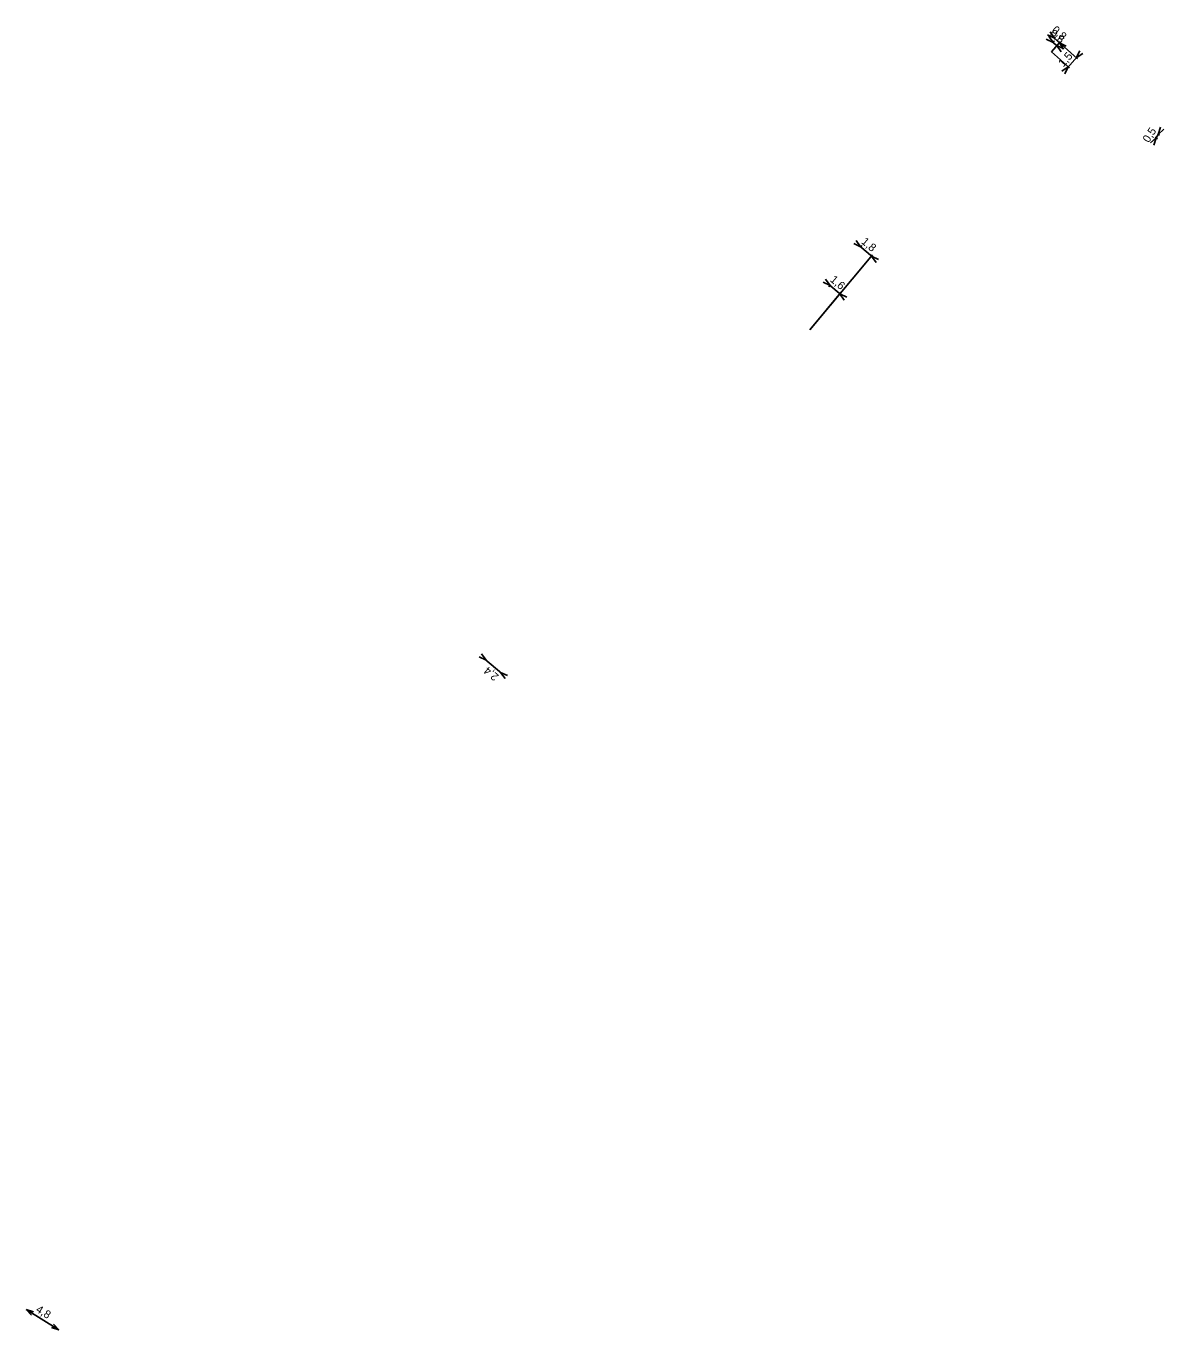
# Model space of a CAD drawing. Extents: x -742845 to -742557, y -1054636 to -1054473.
# Drawn here: x -742845.3 to -742703.1, y -1054636.1 to -1054473.2 of the extents above; entities that cross this region are included whole.
import ezdxf

# ---------------------------------------------------------------- set-up
doc = ezdxf.new("R2010")
doc.units = 0
doc.layers.add('Kota_NN', color=7, linetype='Continuous')
doc.layers.add('Kota_VN', color=7, linetype='Continuous')

msp = doc.modelspace()

# ---------------------------------------------------------------- linework, layer by layer
at = {"layer": 'Kota_NN'}
for p, q in [((-742716.96, -1054475.21), (-742717.82, -1054474.79)), ((-742716.96, -1054475.21), (-742717.5, -1054474.41)), ((-742717.11, -1054475.08), (-742716.36, -1054475.73)), ((-742716.99, -1054475.24), (-742716.83, -1054475.06)), ((-742716.54, -1054475.63), (-742716.38, -1054475.45)), ((-742716.51, -1054475.6), (-742715.64, -1054476.02)), ((-742716.51, -1054475.6), (-742715.97, -1054476.39)), ((-742703.83, -1054486.7), (-742703.54, -1054485.79)), ((-742703.83, -1054486.7), (-742703.12, -1054486.06)), ((-742704.1, -1054487.12), (-742704.81, -1054487.77)), ((-742704.1, -1054487.12), (-742704.4, -1054488.04)), ((-742704.21, -1054487.29), (-742703.72, -1054486.53)), ((-742704.21, -1054487.05), (-742703.93, -1054487.23)), ((-742703.94, -1054486.63), (-742703.66, -1054486.81))]:
    msp.add_line(p, q, dxfattribs=at)
at = {"layer": 'Kota_VN'}
for p, q in [((-742716.8, -1054474.69), (-742717.66, -1054474.26)), ((-742716.8, -1054474.69), (-742717.33, -1054473.89)), ((-742716.95, -1054474.55), (-742716.04, -1054475.37)), ((-742716.81, -1054474.69), (-742716.67, -1054474.54)), ((-742716.81, -1054474.69), (-742713.92, -1054477.25)), ((-742717.19, -1054476.37), (-742716.05, -1054475.09)), ((-742717.19, -1054476.37), (-742714.92, -1054478.38)), ((-742716.19, -1054475.24), (-742715.33, -1054475.67)), ((-742716.19, -1054475.24), (-742715.66, -1054476.04)), ((-742714.07, -1054477.12), (-742713.64, -1054476.26)), ((-742715.2, -1054478.4), (-742713.94, -1054476.97)), ((-742714.07, -1054477.12), (-742713.27, -1054476.59)), ((-742715.07, -1054478.25), (-742715.87, -1054478.78)), ((-742715.07, -1054478.25), (-742715.5, -1054479.11)), ((-742741.02, -1054500.75), (-742741.89, -1054500.34)), ((-742741.02, -1054500.75), (-742741.57, -1054499.96)), ((-742741.17, -1054500.62), (-742739.49, -1054502.04)), ((-742741.08, -1054500.82), (-742740.89, -1054500.6)), ((-742747.39, -1054511.11), (-742739.52, -1054501.75)), ((-742739.65, -1054501.91), (-742738.78, -1054502.32)), ((-742739.65, -1054501.91), (-742739.1, -1054502.7)), ((-742744.85, -1054505.57), (-742745.72, -1054505.16)), ((-742744.85, -1054505.57), (-742745.4, -1054504.78)), ((-742745, -1054505.44), (-742743.45, -1054506.75)), ((-742744.8, -1054505.51), (-742744.98, -1054505.73)), ((-742747.39, -1054511.11), (-742743.48, -1054506.46)), ((-742743.61, -1054506.62), (-742742.74, -1054507.02)), ((-742743.61, -1054506.62), (-742743.06, -1054507.41)), ((-742787.84, -1054552.39), (-742788.71, -1054551.98)), ((-742787.84, -1054552.39), (-742788.4, -1054551.6)), ((-742785.86, -1054554.05), (-742788, -1054552.26)), ((-742787.84, -1054552.39), (-742787.84, -1054552.39)), ((-742786.01, -1054553.93), (-742786.01, -1054553.93)), ((-742786.01, -1054553.93), (-742785.14, -1054554.33)), ((-742786.01, -1054553.93), (-742785.46, -1054554.71)), ((-742845.32, -1054633.55), (-742845.31, -1054633.54)), ((-742845.31, -1054633.54), (-742841.24, -1054636.08)), ((-742845.31, -1054633.54), (-742844.39, -1054633.82)), ((-742845.31, -1054633.54), (-742844.66, -1054634.24)), ((-742841.24, -1054636.08), (-742842.16, -1054635.8)), ((-742841.24, -1054636.08), (-742841.9, -1054635.38)), ((-742841.25, -1054636.09), (-742841.24, -1054636.08))]:
    msp.add_line(p, q, dxfattribs=at)

# ---------------------------------------------------------------- texts
at = {"layer": 'Kota_NN'}
for s, rotation, p in [('0,6', 319.1185, (-742717.48, -1054474.23)), ('0,5', 57.2294, (-742705.02, -1054487.81))]:
    msp.add_text(s, height=1, rotation=rotation, dxfattribs=at).set_placement(p)
at = {"layer": 'Kota_VN'}
for s, rotation, p in [('0,8', 318.4389, (-742717.22, -1054473.78)), ('1,5', 48.4388, (-742715.69, -1054478.35)), ('1,8', 319.9129, (-742741.02, -1054500.23)), ('1,6', 319.9126, (-742744.92, -1054504.99)), ('2,4', 140.0387, (-742786.17, -1054554.32)), ('4,8', 327.9682, (-742844.19, -1054633.77))]:
    msp.add_text(s, height=1, rotation=rotation, dxfattribs=at).set_placement(p)

doc.saveas('drawing.dxf')
